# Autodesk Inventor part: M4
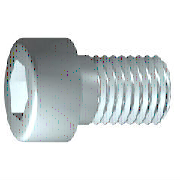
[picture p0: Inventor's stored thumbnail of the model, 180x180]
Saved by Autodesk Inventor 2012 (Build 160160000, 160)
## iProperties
IsCustomPart: 0
Company: 한국ATC센터
Created: 2014-10
Part Number: M4
Material: Steel, Mild
Description: 6각머리 태핑 나사
Document SubType Name: Modeling
Standard: KS B 1003
Designer: KYOUNG IL JANG
Standards Organization: KS
Language: ko-KR
Size Designation: M 4 x 10
Categories: <MemberInstance><Categories><Category DisplayName="조임쇠" InternalName="e4da775c-781d-43d5-af7c-5136215cf5a6" Mnemonic="FSTN"><Category DisplayName="볼트" InternalN
Density: 7.86 g/cm^3
Mass: 2.0371 g
Surface Area: 3.0572 cm^2
Volume: 0.259174 cm^3
Author: KYOUNG IL JANG
Revision Number: 1
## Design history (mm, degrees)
workplane "Work Plane1"
fillet "Fillet2" dims "d30" = 0.1 (= R)
revolve "본체" stored, may be unused: angle "d10" = 90 deg
sketch "스케치2"
  geometry: L1 (0, -4.9)-(0, 4.9) reference; L2 (-4.9, 0)-(4.9, 0) reference; L3 (1.732, 0)-(0.866, -1.5); L4 (0.866, -1.5)-(-0.866, -1.5); L5 (-0.866, -1.5)-(-1.732, 0); L6 (-1.732, 0)-(-0.866, 1.5); L7 (-0.866, 1.5)-(0.866, 1.5); L8 (0.866, 1.5)-(1.732, 0); 2 further points
  constraints: 12 end point, 1 coincident, 1 horizontal alignment, 1 point on line, 12 other
extrude "슬롯" join sketch "스케치2" stored distance "d11" = 10; taper "d12" = 0 deg
body "Solid1"
fillet "모깎기1" dims "d17" = 0.4 (= RR)
feature "스레드" dims "d13" = 8.25 (= GEL), "d14" = 0
chamfer "모따기1" distance "d15" = 0.42941 (= -0.5 x SPD + 0.5 x GD); stored, may be unused: second distance "d16" = 0.42941 (= GUL), angle "d27" = 45 deg
sketch "스케치1"
  geometry: L1 (-1, 0)-(10, 0); L2 (10, 0)-(10, 2); L3 (10, 2)-(1.75, 2); L4 (1.75, 2)-(1.32, 2); L5 (1.32, 2)-(0, 2); L6 (0, 2)-(0, 3.5); L7 (0, 3.5)-(-4, 3.5); L8 (-4, 3.5)-(-4, 1.732); L9 (-4, 1.732)-(-2, 1.732); L10 (-2, 1.732)-(-1, 0); L11 (-6.8, 0)-(12.8, 0) reference; L12 (0, -0.7)-(0, 4.2) reference; L13 (1.75, 2)-(0, 2)
  constraints: 22 end point, 6 parallel, 2 collinear, 2 perpendicular, 1 horizontal, 1 point on line
  dimensions: "d1" = 8.25 distance from line of L3.end L2 (= GEL); "d2" = 0.42952 distance of L4.end L3.end (computed from GAL); "d3" = 4 distance between parallel lines of L8 L6 (= KOH); "d4" = 2 distance of L8.end L9.end (= INTI); "d5" = 60 deg angle of L10 L1; "d6" = 4 diameter of L3 L1 (= GD); "d7" = 4 diameter of L5 L1 (= BDM); "d8" = 3.4641 diameter of L9 L1 (= 1.1547 x SW); "d9" = 7 diameter of L7 L1 (= KOD); "d26" = 10 distance between parallel lines of L12 L2 (= NLG)
other parameters: "GD" = 4 (= NND) [user parameter; used in 2 equation terms], "NLG" = 10 [user parameter; used in 1 equation term], "GEL" = 8.25 [user parameter; used in 2 equation terms], "KOD" = 7 [user parameter; used in 1 equation term], "KOH" = 4 [user parameter; used in 1 equation term], "INTI" = 2 [user parameter; used in 1 equation term], "GAL" = 0.42941 (= 0.61345 x PTC) [user parameter; used in 1 equation term], "GUL" = 0.42941 (= 0.61345 x PTC) [user parameter; used in 1 equation term], "BDM" = 4 (= NND) [user parameter; used in 1 equation term], "SW" = 3 [user parameter; used in 2 equation terms], "RR" = 0.4 [user parameter; used in 1 equation term], "SPD" = 3.14117 (= NND - 1.2269 x PTC) [user parameter; used in 1 equation term], "d19" = 0, "d28" = 0, "d29" = 0, "R" = 0.1 [user parameter; used in 1 equation term], "PHH" = 0.2 [user parameter], "GD1" = 3.14117 (= THREADDIA - 1.2269 x PTC) [user parameter], "THREADDIA" = 4 [user parameter; used in 1 equation term], "FAWI" = 45 deg [user parameter], "TPU" = 14.28571 (computed from PTC) [user parameter], "PTC" = 0.7 [user parameter; used in 5 equation terms], "NND" = 4 [user parameter; used in 3 equation terms], "TOA" = 30 deg [user parameter], "E0" = 3.465 (= 1.155 x SW) [user parameter]
